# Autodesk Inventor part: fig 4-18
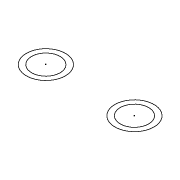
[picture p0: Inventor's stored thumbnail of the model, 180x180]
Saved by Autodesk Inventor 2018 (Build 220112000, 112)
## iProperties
Created: 2005-02
Part Number: fig 4-18
Document SubType Name: Modeling
Designer: CADCIM
Manufacturer: Standard
Standards Organization: Custom
Density: 1 g/cm^3
Material: Generic
Appearance: Default
Author: CADCIM
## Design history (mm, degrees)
sketch "Sketch1"
  geometry: C1 r 7.935 at (-23.563, 7.599); C2 r 7.935 at (12.452, 7.599); C3 r 5.782 at (-23.563, 7.599); C4 r 5.782 at (12.452, 7.599)
  constraints: 4 centre point, 1 coincident, 1 equal radius, 1 other
